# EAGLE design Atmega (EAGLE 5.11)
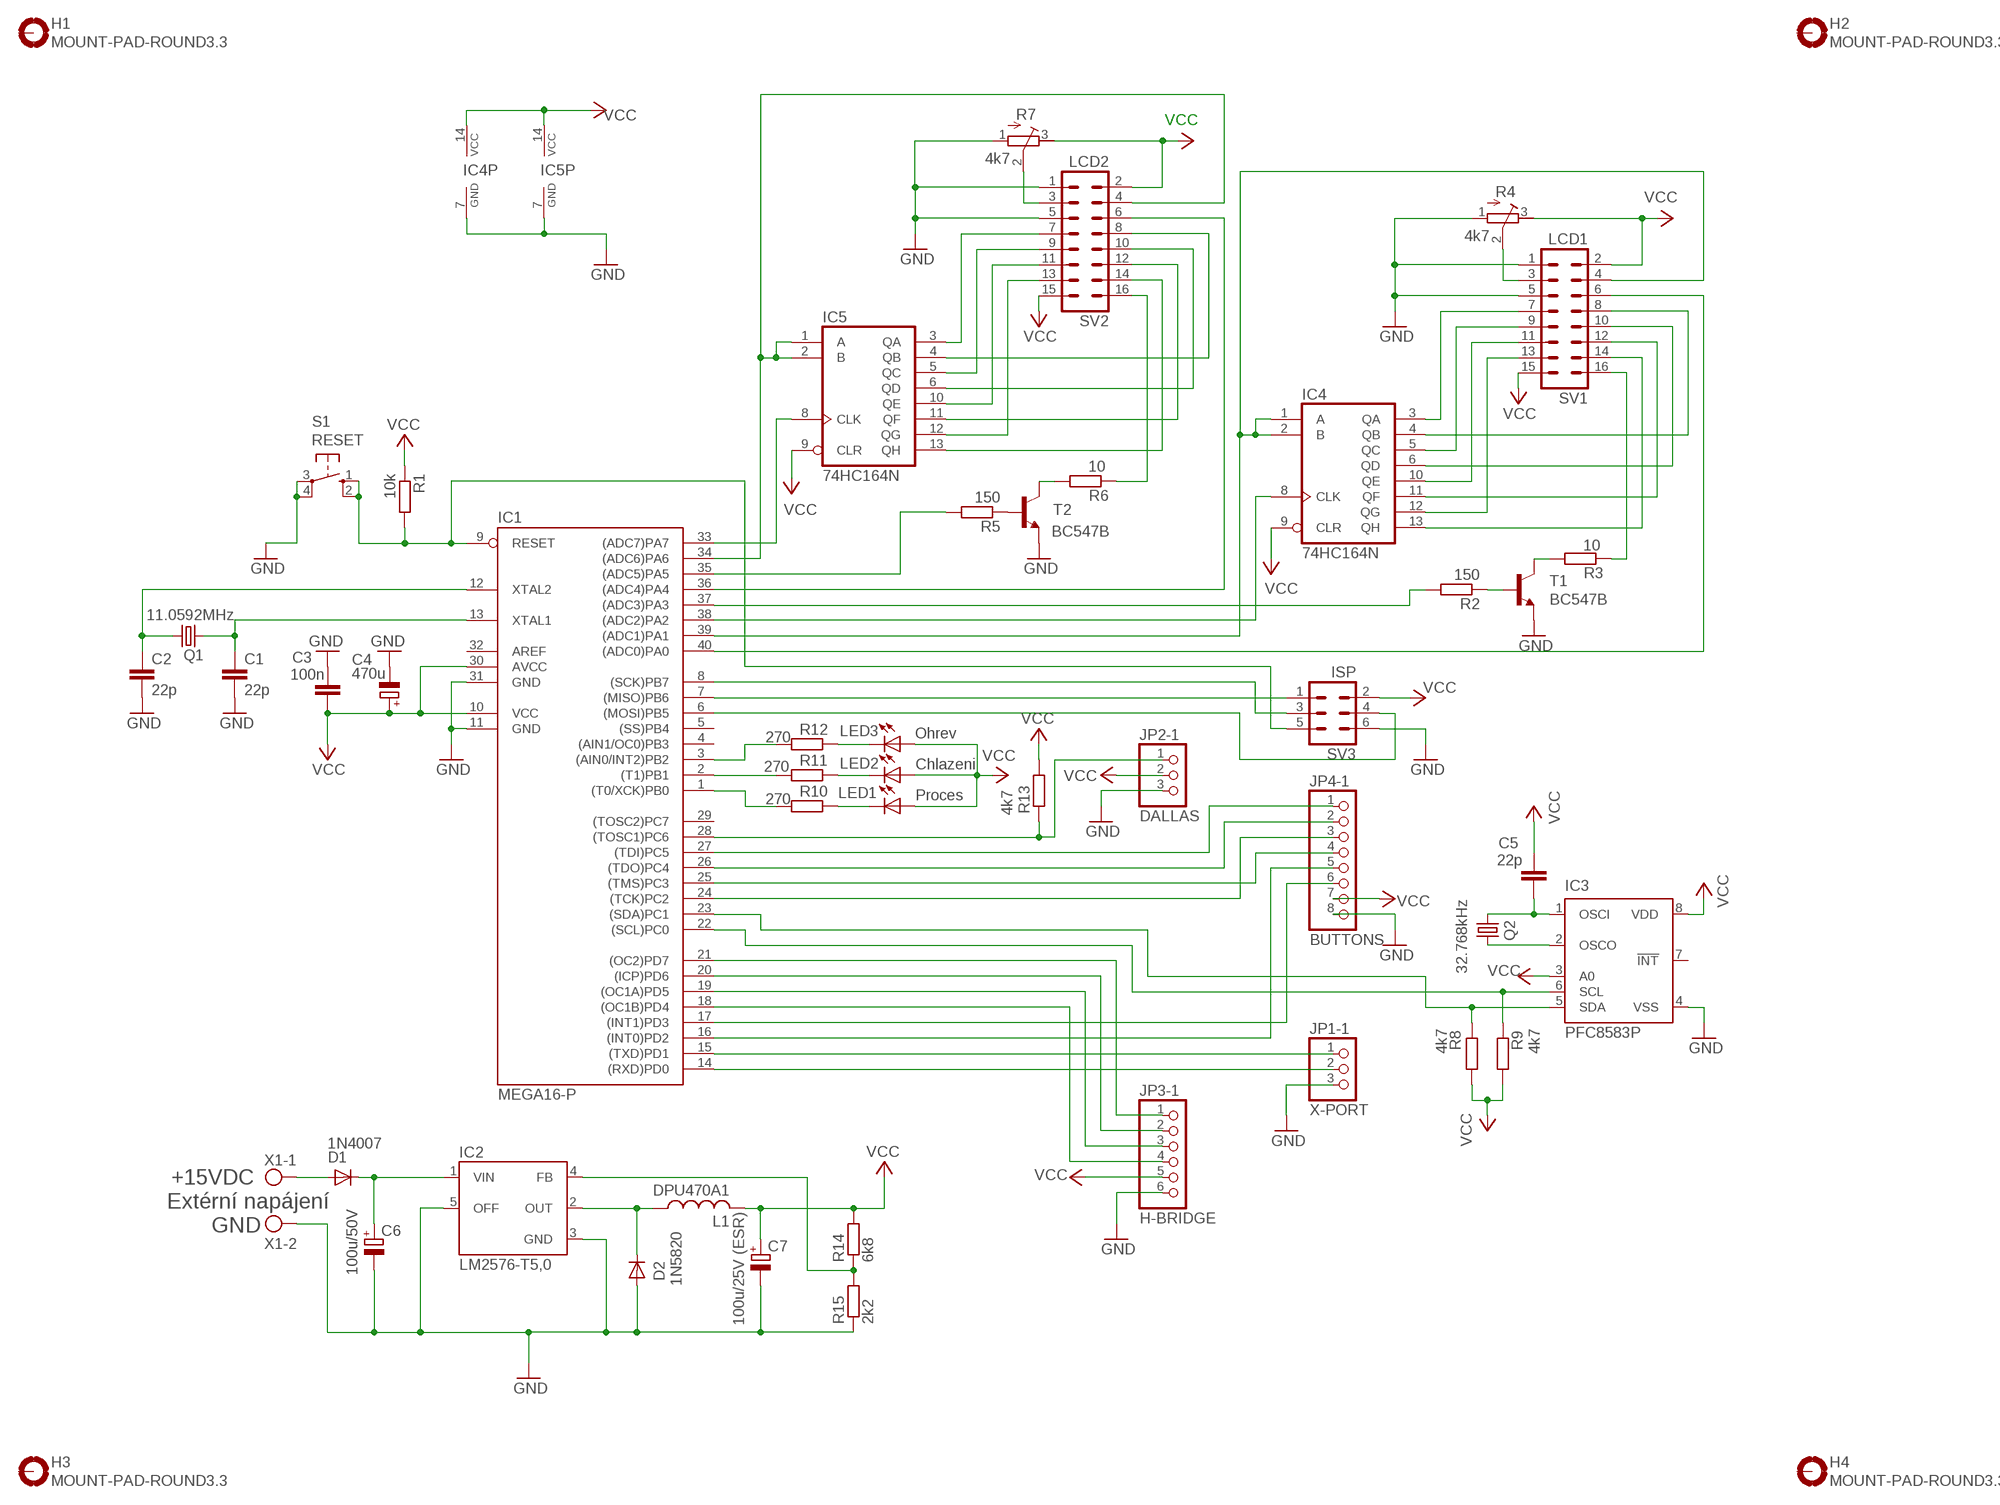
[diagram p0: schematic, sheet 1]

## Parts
C1  22p  C-EU025-030X050  [C025-030X050]
C2  22p  C-EU025-030X050  [C025-030X050]
C3  100n  C-EU025-030X050  [C025-030X050]
C4  470u  CPOL-EUE3.5-8  [E3,5-8]
C5  22p  C-EU025-030X050  [C025-030X050]
C6  100u/50V  CPOL-EUE3.5-8  [E3,5-8]
C7  100u/25V (ESR)  CPOL-EUE3.5-8  [E3,5-8]
D1  1N4007  1N4004  [DO41-10]
D2  1N5820  1N4004  [DO41-10]
H1  MOUNT-PAD-ROUND3.3  [3,3-PAD]
H2  MOUNT-PAD-ROUND3.3  [3,3-PAD]
H3  MOUNT-PAD-ROUND3.3  [3,3-PAD]
H4  MOUNT-PAD-ROUND3.3  [3,3-PAD]
IC1  MEGA16-P  [DIL40]
IC2  LM2576-T5,0  LM2576T  [TO220-5]
IC3  PFC8583P  [DIL08]
IC4  74HC164N  74AC164N  [DIL14]
IC5  74HC164N  74AC164N  [DIL14]
JP1-1  X-PORT  PINHD-1X3  [1X03]
JP2-1  DALLAS  PINHD-1X3  [1X03]
JP3-1  H-BRIDGE  PINHD-1X6  [1X06]
JP4-1  BUTTONS  PINHD-1X8  [1X08]
L1  DPU470A1  L-USIR-4  [IR-4]
LED1  Proces  LED5MM  [LED5MM]
LED2  Chlazeni  LED5MM  [LED5MM]
LED3  Ohrev  LED5MM  [LED5MM]
Q1  11.0592MHz  CRYSTALHC49U-V  [HC49U-V]
Q2  32.768kHz  CRYSTALTC26V  [TC26V]
R1  10k  R-EU_0207/7  [0207/7]
R2  150  R-EU_0207/7  [0207/7]
R3  10  R-EU_0207/7  [0207/7]
R4  4k7  R-TRIMM64Y  [RTRIM64Y]
R5  150  R-EU_0207/7  [0207/7]
R6  10  R-EU_0207/7  [0207/7]
R7  4k7  R-TRIMM64Y  [RTRIM64Y]
R8  4k7  R-EU_0207/7  [0207/7]
R9  4k7  R-EU_0207/7  [0207/7]
R10  270  R-EU_0207/7  [0207/7]
R11  270  R-EU_0207/7  [0207/7]
R12  270  R-EU_0207/7  [0207/7]
R13  4k7  R-EU_0207/7  [0207/7]
R14  6k8  R-EU_0207/7  [0207/7]
R15  2k2  R-EU_0207/7  [0207/7]
S1  RESET  10-XX  [B3F-10XX]
SV1  LCD1  ML16  [ML16]
SV2  LCD2  ML16  [ML16]
SV3  ISP  ML6  [ML6]
T1  BC547B  [TO92]
T2  BC547B  [TO92]
X1  Extérní napájení  AK300/2  [AK300/2]

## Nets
E_LCD1: IC1.40((ADC0)PA0) SV1.6
E_LCD2: IC1.36((ADC4)PA4) SV2.6
GND: C1.2 C2.2 C3.1 C4.- C6.- C7.- D2.A IC1.11(GND) IC1.31(GND) IC2.3(GND) IC2.5(OFF) IC3.4(VSS) IC4.7(GND) IC5.7(GND) JP1-1.3 JP2-1.3 JP3-1.6 JP4-1.8 R4.1(E) R7.1(E) R15.1 S1.3(P) S1.4(P1) SV1.1 SV1.5 SV2.1 SV2.5 SV3.6 T1.1(E) T2.1(E) X1.2
N$1: IC1.38((ADC2)PA2) IC4.8(CLK)
N$2: IC1.39((ADC1)PA1) IC4.1(A) IC4.2(B) SV1.4
N$3: IC1.37((ADC3)PA3) R2.2
N$4: R2.1 T1.2(B)
N$5: R3.2 T1.3(C)
N$6: R3.1 SV1.16
N$7: IC4.3(QA) SV1.7
N$8: IC4.5(QC) SV1.9
N$9: IC4.4(QB) SV1.8
N$10: IC4.6(QD) SV1.10
N$11: IC4.10(QE) SV1.11
N$12: IC4.11(QF) SV1.12
N$13: IC4.12(QG) SV1.13
N$14: IC4.13(QH) SV1.14
N$15: IC1.15((TXD)PD1) JP1-1.1
N$16: R4.2(S) SV1.3
N$17: IC1.14((RXD)PD0) JP1-1.2
N$18: IC1.33((ADC7)PA7) IC5.8(CLK)
N$19: IC1.34((ADC6)PA6) IC5.1(A) IC5.2(B) SV2.4
N$20: IC1.35((ADC5)PA5) R5.2
N$21: R5.1 T2.2(B)
N$22: R6.2 T2.3(C)
N$23: R6.1 SV2.16
N$24: IC5.3(QA) SV2.7
N$25: IC5.5(QC) SV2.9
N$26: IC5.4(QB) SV2.8
N$27: IC5.6(QD) SV2.10
N$28: IC5.10(QE) SV2.11
N$29: IC5.11(QF) SV2.12
N$30: IC5.12(QG) SV2.13
N$31: IC5.13(QH) SV2.14
N$32: R7.2(S) SV2.3
N$33: IC2.4(FB) R14.1 R15.2
N$34: C1.1 IC1.13(XTAL1) Q1.2
N$35: C2.1 IC1.12(XTAL2) Q1.1
N$36: D1.A X1.1
N$37: IC1.1((T0/XCK)PB0) R10.1
N$38: IC1.2((T1)PB1) R11.1
N$39: IC1.21((OC2)PD7) JP3-1.1
N$40: IC1.3((AIN0/INT2)PB2) R12.1
N$41: IC1.26((TDO)PC4) JP4-1.2
N$42: C5.2 IC3.1(OSCI) Q2.1
N$43: IC3.2(OSCO) Q2.2
N$44: IC1.27((TDI)PC5) JP4-1.1
N$45: D2.C IC2.2(OUT) L1.1
N$46: C6.+ D1.C IC2.1(VIN)
N$47: IC1.23((SDA)PC1) IC3.5(SDA) R8.1
N$48: IC1.22((SCL)PC0) IC3.6(SCL) R9.1
N$50: LED1.K(C) R10.2
N$51: LED2.K(C) R11.2
N$52: LED3.K(C) R12.2
N$53: IC1.24((TCK)PC2) JP4-1.3
N$54: IC1.25((TMS)PC3) JP4-1.4
N$55: IC1.16((INT0)PD2) JP4-1.5
N$56: IC1.17((INT1)PD3) JP4-1.6
N$57: IC1.6((MOSI)PB5) SV3.4
N$58: IC1.7((MISO)PB6) SV3.1
N$59: IC1.8((SCK)PB7) SV3.3
N$60: IC1.28((TOSC1)PC6) JP2-1.1 R13.1
N$61: IC1.9(RESET) R1.2 S1.1(S) S1.2(S1) SV3.5
N$62: IC1.20((ICP)PD6) JP3-1.2
N$63: IC1.19((OC1A)PD5) JP3-1.3
N$64: IC1.18((OC1B)PD4) JP3-1.4
VCC: C3.2 C4.+ C5.1 C7.+ IC1.10(VCC) IC1.30(AVCC) IC3.3(A0) IC3.8(VDD) IC4.9(CLR) IC4.14(VCC) IC5.9(CLR) IC5.14(VCC) JP2-1.2 JP3-1.5 JP4-1.7 L1.2 LED1.A LED2.A LED3.A R1.1 R4.3(A) R7.3(A) R8.2 R9.2 R13.2 R14.2 SV1.2 SV1.15 SV2.2 SV2.15 SV3.2
Unconnected: H1.B3,3(MOUNT) H2.B3,3(MOUNT) H3.B3,3(MOUNT) H4.B3,3(MOUNT) IC1.4((AIN1/OC0)PB3) IC1.5((SS)PB4) IC1.29((TOSC2)PC7) IC1.32(AREF) IC3.7(!INT)

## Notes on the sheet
- +15VDC
- GND

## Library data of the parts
C1-C3 C5 = rcl:C-EU: CAPACITOR, European symbol
C4 C6 C7 = rcl:CPOL-EU: POLARIZED CAPACITOR, European symbol
D1 D2 = diode:1N4004: DIODE
H1-H4 = holes:MOUNT-PAD-ROUND: MOUNTING PAD, round
IC1 = atmel:MEGA16-P: MICROCONTROLLER 16 Kbytes FLASH 1 kbytes SRAM 512 bytes EEPROM USART 8-channel 10 bit ADC Source: avr.lbr; MPN: ATMEGA16-16PU; OC_FARNELL: 9171142; OC_NEWARK: 01M6885
IC2 = v-reg-3:LM2576: National Semiconductor 3.0A "Simple Switcher"(c) 52kHz, Vout 1.23-37V (HV: 57V), Vin 40V (HV: 60V), 50µA standby current
IC3 = micro-philips:PFC8583: I2C-Bus CLOCK/CALENDAR; OC_FARNELL: unknown; OC_NEWARK: unknown
IC4 IC5 = 74xx-eu:74*164: 8-bit parallel out SHIFT REGISTER
JP1-1 JP2-1 = pinhead:PINHD-1X3: PIN HEADER
JP3-1 = pinhead:PINHD-1X6: PIN HEADER
JP4-1 = pinhead:PINHD-1X8: PIN HEADER
L1 = rcl:L-US: INDUCTOR, American symbol
LED1-LED3 = led:LED: LED
Q1 = crystal:CRYSTAL: CRYSTAL; OC_FARNELL: 1666969; OC_NEWARK: unknown
Q2 = crystal:CRYSTAL: CRYSTAL; OC_FARNELL: unknown; OC_NEWARK: unknown
R1-R3 R5 R6 R8-R15 = rcl:R-EU_: RESISTOR, European symbol
R4 R7 = rcl:R-TRIMM: Trimm resistor
S1 = switch-omron:10-XX: OMRON SWITCH; MPN: B3F-1000; OC_FARNELL: 176432; OC_NEWARK: 36M3542
SV1 SV2 = con-harting-ml:ML16: HARTING; OC_FARNELL: unknown; OC_NEWARK: unknown
SV3 = con-harting-ml:ML6: HARTING; OC_FARNELL: unknown; OC_NEWARK: unknown
T1 T2 = transistor-npn:BC547*: NPN Transistor
X1 = con-ptr500:AK300/2: CONNECTOR; OC_FARNELL: unknown; OC_NEWARK: unknown

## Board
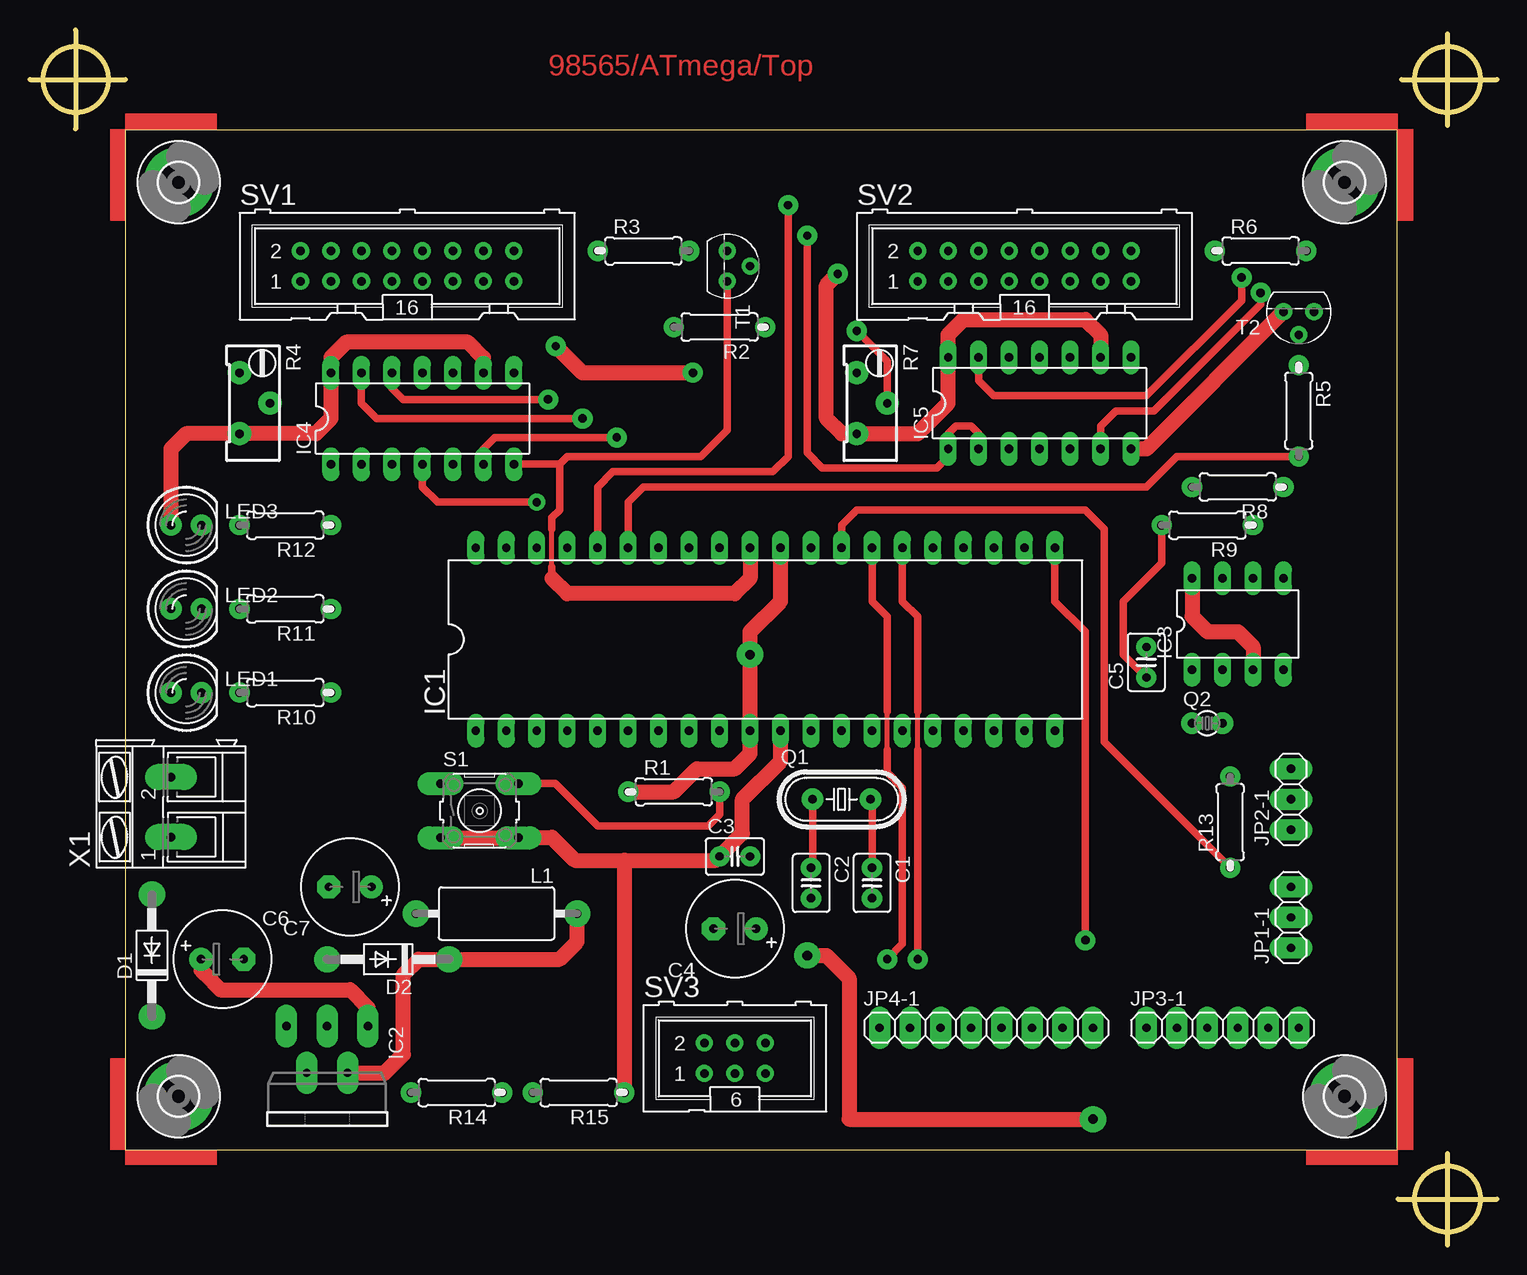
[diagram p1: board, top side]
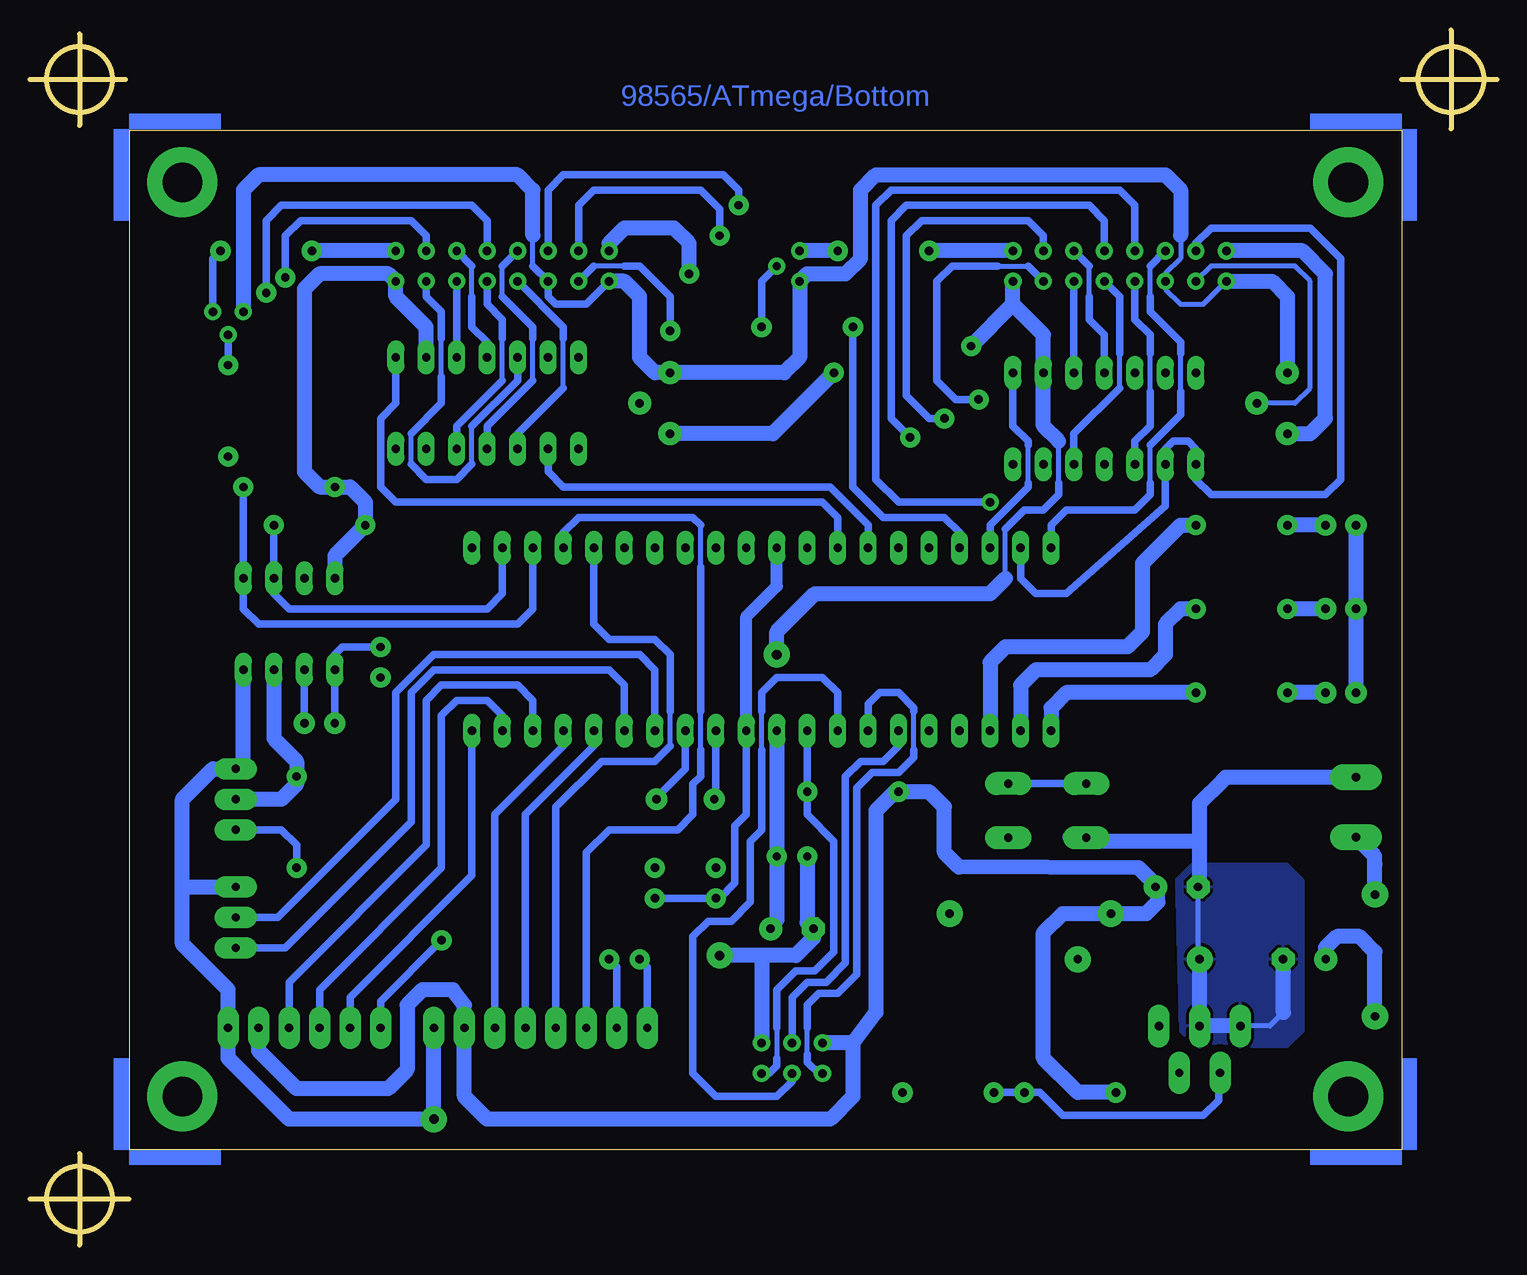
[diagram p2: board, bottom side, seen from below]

Size 122.24 x 101.28 mm. Coordinates in mm from the lower left corner, seen from the top.
Outline: 113.98,3.81 122.24,3.81
Outline: 118.11,7.62 118.11,0
Outline: 114.3,97.16 122.24,97.16
Outline: 118.11,100.97 118.11,93.34
Outline: 0,97.16 7.94,97.16
Outline: 3.81,101.28 3.81,93.03
Outline: 7.94,7.94 113.94,7.94 113.94,92.94 7.94,92.94 7.94,7.94
Outline: circle at 3.81,97.16 radius 2.73
Outline: circle at 118.11,97.16 radius 2.73
Outline: circle at 118.11,3.81 radius 2.73
Copper layers (1*16): Top 0.035mm / dielectric 1.5mm / Bottom 0.035mm
Design rules "default *": minimum track width 10mil, minimum drill 24mil, track to track 10mil, track to pad 10mil, pad to pad 10mil, via to via 8mil, smd to smd 8mil, copper to edge 40mil, drill to drill 8mil, minimum pad ring 10mil, minimum via ring 8mil, stop-mask expansion 4mil, vias tented up to drill 0mil, thermal gap 10mil

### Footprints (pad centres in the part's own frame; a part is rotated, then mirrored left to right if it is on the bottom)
C025-030X050 = drill 0.7 pad 1.676 round: 1 -1.27,0; 2 1.27,0
E3,5-8 = drill 0.7 pad 1.93 round: + -1.778,0 | drill 0.7 pad 1.93 octagon: - 1.778,0
DO41-10 = drill 0.7 pad 2.184 round: A 5.08,0; C -5.08,0
3,3-PAD = drill 3.3 pad 5.842 round: B3,3 0,0
DIL40 = drill 0.7 pad 1.422 long: 1 -24.13,-7.62; 2 -21.59,-7.62; 3 -19.05,-7.62; 4 -16.51,-7.62; 5 -13.97,-7.62; 6 -11.43,-7.62; 7 -8.89,-7.62; 8 -6.35,-7.62; 9 -3.81,-7.62; 10 -1.27,-7.62; 11 1.27,-7.62; 12 3.81,-7.62; 13 6.35,-7.62; 14 8.89,-7.62; 15 11.43,-7.62; 16 13.97,-7.62; 17 16.51,-7.62; 18 19.05,-7.62; 19 21.59,-7.62; 20 24.13,-7.62; 21 24.13,7.62; 22 21.59,7.62; 23 19.05,7.62; 24 16.51,7.62; 25 13.97,7.62; 26 11.43,7.62; 27 8.89,7.62; 28 6.35,7.62; 29 3.81,7.62; 30 1.27,7.62; 31 -1.27,7.62; 32 -3.81,7.62; 33 -6.35,7.62; 34 -8.89,7.62; 35 -11.43,7.62; 36 -13.97,7.62; 37 -16.51,7.62; 38 -19.05,7.62; 39 -21.59,7.62; 40 -24.13,7.62
TO220-5 = drill 0.7 pad 1.778 long: 1 -3.4,-8.4; 2 -1.7,-4.5; 3 0,-8.4; 4 1.7,-4.5; 5 3.4,-8.4
DIL08 = drill 0.7 pad 1.422 long: 1 -3.81,-3.81; 2 -1.27,-3.81; 3 1.27,-3.81; 4 3.81,-3.81; 5 3.81,3.81; 6 1.27,3.81; 7 -1.27,3.81; 8 -3.81,3.81
DIL14 = drill 0.7 pad 1.422 long: 1 -7.62,-3.81; 2 -5.08,-3.81; 3 -2.54,-3.81; 4 0,-3.81; 5 2.54,-3.81; 6 5.08,-3.81; 7 7.62,-3.81; 8 7.62,3.81; 9 5.08,3.81; 10 2.54,3.81; 11 0,3.81; 12 -2.54,3.81; 13 -5.08,3.81; 14 -7.62,3.81
1X03 = drill 0.7 pad 1.778 long: 1 -2.54,0; 2 0,0; 3 2.54,0
1X06 = drill 0.7 pad 1.778 long: 1 -6.35,0; 2 -3.81,0; 3 -1.27,0; 4 1.27,0; 5 3.81,0; 6 6.35,0
1X08 = drill 0.7 pad 1.778 long: 1 -8.89,0; 2 -6.35,0; 3 -3.81,0; 4 -1.27,0; 5 1.27,0; 6 3.81,0; 7 6.35,0; 8 8.89,0
IR-4 = drill 0.7 pad 2.184 round: 1 -6.705,0; 2 6.73,0
LED5MM = drill 0.7 pad 1.778 round: A -1.27,0; K 1.27,0
HC49U-V = drill 0.7 pad 1.778 round: 1 -2.413,0; 2 2.413,0
TC26V = drill 0.7 pad 1.778 round: 1 -1.27,0; 2 1.27,0
0207/7 = drill 0.7 pad 1.676 round: 1 -3.81,0; 2 3.81,0
RTRIM64Y = drill 0.7 pad 1.93 round: 1 0,-2.54; 2 -2.54,0; 3 0,2.54
B3F-10XX = drill 0.7 pad 1.93 long: 1 -3.251,2.261; 2 3.251,2.261; 3 -3.251,-2.261; 4 3.251,-2.261
ML16 = drill 0.7 pad 1.422 round: 1 -8.89,-1.27; 2 -8.89,1.27; 3 -6.35,-1.27; 4 -6.35,1.27; 5 -3.81,-1.27; 6 -3.81,1.27; 7 -1.27,-1.27; 8 -1.27,1.27; 9 1.27,-1.27; 10 1.27,1.27; 11 3.81,-1.27; 12 3.81,1.27; 13 6.35,-1.27; 14 6.35,1.27; 15 8.89,-1.27; 16 8.89,1.27
ML6 = drill 0.7 pad 1.422 round: 1 -2.54,-1.27; 2 -2.54,1.27; 3 0,-1.27; 4 0,1.27; 5 2.54,-1.27; 6 2.54,1.27
TO92 = drill 0.7 pad 1.422 round: 1 1.27,0; 2 0,1.905; 3 -1.27,0
AK300/2 = drill 0.7 pad 2.184 long: 1 -2.515,0; 2 2.489,0

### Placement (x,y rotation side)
C1  70.17,30.16 270 top
C2  65.09,30.16 270 top
C3  58.74,32.39 0 top
C4  58.74,26.35 180 top
C5  93.03,48.58 90 top
C6  16.03,23.81 0 top
C7  26.67,29.84 180 top
D1  10.16,24.13 90 top
D2  29.84,23.81 180 top
H1  12.38,12.38 0 top
H2  12.38,88.58 0 top
H3  109.54,12.38 0 top
H4  109.54,88.58 0 top
IC1  61.28,50.48 0 top
IC2  24.77,9.84 180 top
IC3  100.65,51.75 0 top
IC4  32.7,68.9 0 top
IC5  84.14,70.17 0 top
JP1-1  105.09,27.3 90 top
JP2-1  105.09,37.15 90 top
JP3-1  99.38,18.1 0 top
JP4-1  79.69,18.1 0 top
L1  38.89,27.62 180 top
LED1  13.02,46.04 0 top
LED2  13.02,53.02 0 top
LED3  13.02,60.01 0 top
Q1  67.63,37.15 0 top
Q2  98.11,43.5 0 top
R1  53.66,37.78 0 top
R2  57.47,76.52 180 top
R3  51.12,82.87 0 top
R4  17.46,70.17 180 top
R5  105.73,69.53 270 top
R6  102.55,82.87 0 top
R7  68.9,70.17 180 top
R8  100.65,63.18 180 top
R9  98.11,60.01 180 top
R10  21.27,46.04 180 top
R11  21.27,53.02 180 top
R12  21.27,60.01 180 top
R13  100.01,35.24 90 top
R14  35.56,12.7 180 top
R15  45.72,12.7 180 top
S1  37.47,36.2 0 top
SV1  31.43,81.6 0 top
SV2  82.87,81.6 0 top
SV3  58.74,15.56 0 top
T1  58.1,81.6 270 top
T2  105.73,77.79 180 top
U$1  [ANGLE-ARROW-NW1-16]  7.94,93.03 0 top
U$2  [ANGLE-ARROW-NW1-16]  113.98,93.03 270 top
U$3  [ANGLE-ARROW-NW1-16]  113.98,7.94 180 top
U$4  [ANGLE-ARROW-NW1-16]  7.94,7.94 90 top
X1  11.75,36.51 90 top

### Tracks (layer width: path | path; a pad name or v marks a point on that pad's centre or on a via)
E_LCD1
  Bottom 0.406: 28.89,79.06 28.89,81.6 | 26.35,71.12 26.35,74.3 | 28.89,63.5 28.89,66.67
  Bottom 0.61: 28.89,81.6 SV1.6 | 28.89,79.06 28.89,77.79 26.35,75.25 26.35,74.3 | 28.89,66.67 26.35,69.22 26.35,71.12 | IC1.40 37.15,60.01 35.88,61.28 30.16,61.28 28.89,62.55 28.89,63.5
E_LCD2  (via drill 0.7 pad 1.68)
  Top 0.61: v63.18,86.68 63.18,65.72 61.91,64.45 48.58,64.45 47.31,63.18 IC1.36
  Bottom 0.61: SV2.6 79.06,87.95 77.79,89.22 64.45,89.22 63.18,87.95 v63.18,86.68
GND  (via drill 0.8 pad 2.18)
  Top 0.406: 43.5,55.56 43.5,55.88 | 43.5,56.52 43.5,59.69
  Top 0.61: T1.1 58.1,67.95 55.88,65.72 44.77,65.72 44.13,65.09 | 43.5,55.88 43.5,56.52 | 43.5,59.69 43.5,60.64 44.13,61.28 44.13,65.09 | 44.13,65.09 IC4.7
  Top 1.27: T2.1 93.03,66.36 IC5.7 | IC1.11 62.55,40.32 59.37,37.15 59.37,34.29 C3.1 57.15,32.07 49.53,32.07 | v88.58,10.48 68.26,10.48 68.26,22.22 66.36,24.13 v64.77,24.13 | 43.5,55.56 44.77,54.29 58.74,54.29 60.01,55.56 IC1.31 | S1.3 S1.4 39.17,33.97 43.5,33.97 45.4,32.07 49.53,32.07 | 49.53,32.07 R15.1
  Bottom 0.406: SV1.1 24.45,78.42 26.35,78.42 27.62,79.69 SV1.5 27.62,80.96 26.35,82.23 26.35,84.14 | 80.33,81.6 80.33,84.14 | C7.- 24.89,22.99 D2.A | IC2.5 18.9,18.24 17.78,19.37
  Bottom 0.61: SV2.1 75.88,78.42 78.42,78.42 79.06,79.06 SV2.5 80.33,81.6 | C1.2 C2.2 64.77,28.89 63.5,30.16 63.5,34.93 62.55,35.88 IC1.11
  Bottom 1.016: IC1.11 62.55,52.39 60.01,54.93 IC1.31
  Bottom 1.27: R4.1 17.46,79.06 18.73,80.33 SV1.1 | 26.35,84.14 26.35,87.95 27.62,89.22 51.75,89.22 53.02,87.95 53.02,82.23 54.29,80.96 57.47,80.96 T1.1 58.1,73.98 59.37,72.71 R7.1 70.17,72.71 71.44,73.98 71.44,79.06 72.71,80.33 SV2.1 | 80.33,84.14 80.33,87.95 81.6,89.22 103.19,89.22 104.46,87.95 T2.1 | IC3.4 104.46,40.32 JP2-1.3 107,39.69 109.54,37.15 109.54,29.84 | C3.1 57.47,26.86 C4.- 56.96,25.59 58.42,24.13 61.28,24.13 | JP4-1.8 v88.58,10.48 100.65,10.48 105.73,15.56 JP3-1.6 105.73,21.27 109.54,25.08 109.54,29.84 | 35.56,33.97 33.93,33.97 S1.3 33.93,33.66 24.77,33.66 | 61.28,24.13 SV3.6 | D2.A IC2.3 IC2.5 | 17.78,19.37 17.78,22.83 C6.- | C7.- 24.89,29.97 24.77,29.97 24.77,33.66 | 109.54,29.84 JP1-1.3 | 61.28,24.13 v64.77,24.13 | 24.77,33.66 24.77,36.83 22.86,38.73 22.59,39 X1.2
  pour Bottom (isolate 0.61): 25.4,31.75 17.46,31.75 16.19,30.48 16.19,17.78 17.46,16.51 25.08,16.51 26.35,17.78 26.67,30.48
N$1
  Bottom 0.406: 39.05,63.5 39.05,66.67
  Bottom 0.61: IC4.8 40.32,68.26 39.05,66.99 39.05,66.67 | IC1.38 42.23,60.01 39.05,63.18 39.05,63.5
N$2
  Bottom 0.61: IC1.39 39.69,55.56 38.42,54.29 35.88,54.29 27.62,61.59 IC4.2 27.62,66.36 26.99,66.99 25.72,66.99 25.08,66.36 IC4.1 25.08,63.82 23.81,62.55 14.29,62.55 13.02,63.82 13.02,82.23 15.56,84.77 23.81,84.77 25.08,83.5 SV1.4
N$3
  Bottom 0.61: IC1.37 44.77,59.37 46.04,60.64 51.12,60.64 53.66,63.18 R2.2
N$4
  Bottom 0.61: T1.2 61.28,80.33 R2.1
N$5
  Bottom 1.27: R3.2 T1.3
N$6
  Bottom 1.27: SV1.16 R3.1
N$7
  Bottom 0.406: 28.89,71.12 28.89,74.3
  Bottom 0.61: SV1.7 30.16,77.15 28.89,75.88 28.89,74.3 | IC4.3 30.16,66.99 28.89,68.26 28.89,71.12
N$8
  Bottom 0.406: 31.43,71.44 31.43,74.3
  Bottom 0.61: SV1.9 31.43,79.06 31.43,74.3 | 31.43,71.44 35.24,67.63 IC4.5
N$9  (via drill 0.7 pad 1.42)
  Top 0.61: v42.23,61.91 33.97,61.91 32.7,63.18 IC4.4
  Bottom 0.61: SV1.8 30.16,86.68 31.43,87.95 50.48,87.95 51.75,86.68 51.75,63.82 49.85,61.91 v42.23,61.91
N$10  (via drill 0.7 pad 1.68)
  Top 0.61: v48.9,67.31 38.73,67.31 37.78,66.36 IC4.6
  Bottom 0.61: SV1.10 32.7,85.41 33.97,86.68 49.21,86.68 50.48,85.41 50.48,68.9 v48.9,67.31
N$11
  Bottom 0.61: IC4.10 SV1.11
N$12
  Bottom 0.406: 33.97,79.06 33.97,81.6
  Bottom 0.61: IC4.11 32.7,75.88 33.97,77.15 33.97,79.06 | 33.97,81.6 SV1.12
N$13  (via drill 0.7 pad 1.68)
  Top 0.61: v43.18,70.48 31.11,70.48 30.16,71.44 IC4.12
  Bottom 0.406: 41.59,81.6 39.05,81.6
  Bottom 0.61: 39.05,81.6 SV1.13 | 41.59,81.6 45.4,81.6 46.67,80.33 46.67,72.07 45.09,70.48 v43.18,70.48
N$14  (via drill 0.7 pad 1.68)
  Top 0.61: v46.04,68.9 28.89,68.9 27.62,70.17 IC4.13
  Bottom 0.61: SV1.14 37.78,84.14 39.05,85.41 47.94,85.41 49.21,84.14 49.21,70.8 47.31,68.9 v46.04,68.9
N$15
  Bottom 0.61: IC1.15 72.71,46.67 73.98,47.94 88.58,47.94 90.49,46.04 90.49,35.24 100.97,24.77 JP1-1.1 103.19,24.77
N$16
  Bottom 0.406: R4.2 16.83,70.17 15.56,71.44 15.56,80.33 16.83,81.6 23.81,81.6 SV1.3
N$17
  Bottom 0.61: 103.82,27.3 JP1-1.2 101.6,27.3 91.76,37.15 91.76,46.04 88.58,49.21 71.44,49.21 70.17,47.94 IC1.14
N$18
  Bottom 0.61: IC5.8 91.76,70.17 93.03,68.9 93.03,63.18 91.76,61.91 56.2,61.91 54.93,60.64 IC1.33
N$19  (via drill 0.7 pad 1.68)
  Top 0.61: v64.77,84.14 64.77,66.04 66.04,64.77 75.56,64.77 76.52,65.72 IC5.1 76.52,67.63 77.15,68.26 78.42,68.26 79.06,67.63 IC5.2
  Bottom 0.61: SV2.4 76.52,86.68 75.25,87.95 66.36,87.95 64.77,86.36 v64.77,84.14 | IC1.34 52.39,60.01 55.56,63.18 77.79,63.18 79.06,64.45 IC5.2
N$20
  Top 0.61: IC1.35 49.85,61.91 51.12,63.18 93.03,63.18 95.57,65.72 R5.2
N$21
  Bottom 0.61: R5.1 T2.2
N$22
  Bottom 0.61: T2.3 107,82.23 R6.2
N$23
  Bottom 1.27: SV2.16 R6.1
N$24
  Bottom 0.406: 77.79,71.44 77.79,75.56
  Bottom 0.61: SV2.7 77.79,76.52 77.79,75.56 | 77.79,71.44 81.6,67.63 IC5.3
N$25
  Bottom 0.406: 82.87,72.07 82.87,75.56
  Bottom 0.61: SV2.9 84.14,78.42 82.87,77.15 82.87,75.56 | 82.87,72.07 86.68,68.26 IC5.5
N$26
  Bottom 0.406: 82.87,79.06 82.87,81.6 | 80.33,72.07 80.33,75.56
  Bottom 0.61: 82.87,81.6 SV2.8 | 82.87,79.06 80.33,76.52 80.33,75.56 | 80.33,72.07 84.14,68.26 IC5.4
N$27  (via drill 0.7 pad 1.68)
  Top 0.61: v102.55,79.38 102.55,78.42 93.66,69.53 90.49,69.53 89.22,68.26 IC5.6
  Bottom 0.61: SV2.10 84.14,85.41 85.41,86.68 101.28,86.68 102.55,85.41 v102.55,79.38
N$28
  Bottom 0.61: IC5.10 SV2.11
N$29
  Bottom 0.406: 85.41,79.06 85.41,81.6
  Bottom 0.61: IC5.11 84.14,75.25 85.41,76.52 85.41,79.06 | 85.41,81.6 SV2.12
N$30
  Bottom 0.406: 87.95,72.39 87.95,75.56 | 90.49,65.09 90.49,67.63 | 85.41,65.09 85.41,68.26
  Bottom 0.61: SV2.13 89.22,79.06 87.95,77.79 87.95,75.56 | 90.49,67.63 87.95,70.17 87.95,72.39 | 90.49,65.09 89.22,63.82 86.68,63.82 85.41,65.09 | 85.41,68.26 81.6,72.07 IC5.12
N$31  (via drill 0.7 pad 1.68)
  Top 0.61: v100.97,80.64 100.97,78.74 93.03,70.8 80.33,70.8 79.06,72.07 IC5.13
  Bottom 0.61: SV2.14 89.22,84.14 90.49,85.41 99.69,85.41 100.97,84.14 v100.97,80.64
N$32  (via drill 0.7 pad 1.68)
  Top 0.61: v68.9,76.2 71.44,73.66 R7.2
  Bottom 0.406: 72.71,81.6 75.25,81.6
  Bottom 0.61: v68.9,76.2 68.9,79.06 71.44,81.6 72.71,81.6 | 75.25,81.6 SV2.3
N$33
  Bottom 0.61: R15.2 R14.1 38.1,12.7 36.2,10.79 24.45,10.79 23.18,12.07 23.18,14.23 IC2.4
N$34
  Top 0.406: 70.17,37.02 Q1.2
  Top 0.61: C1.1 70.17,37.02
  Bottom 0.406: 70.17,37.15 70.17,37.27 Q1.2
  Bottom 0.61: IC1.13 67.63,39.69 70.17,37.15
N$35
  Top 0.406: C2.1 65.21,31.56
  Top 0.61: 65.21,31.56 Q1.1
  Bottom 0.61: IC1.12 65.09,37.91 Q1.1
N$36
  Bottom 1.27: X1.1 10.19,32.41 10.16,31.75 D1.A
N$37
  Bottom 1.27: R10.1 35.88,46.04 37.15,44.77 IC1.1
N$38
  Bottom 1.27: IC1.2 39.69,46.67 38.42,47.94 28.89,47.94 27.62,49.21 27.62,51.75 26.35,53.02 R11.1
N$39  (via drill 0.7 pad 1.68)
  Top 0.61: IC1.21 85.41,53.66 87.95,51.12 v87.95,25.4
  Bottom 0.61: JP3-1.1 93.03,20.32 v87.95,25.4
N$40
  Bottom 1.27: IC1.3 42.23,48.58 40.96,49.85 30.8,49.85 29.53,51.12 29.53,56.83 26.35,60.01 R12.1
N$41  (via drill 0.7 pad 1.68)
  Top 0.406: 73.98,41.27 73.98,44.45
  Top 0.61: IC1.26 72.71,53.66 73.98,52.39 73.98,44.45 | v73.98,23.81 73.98,41.27
  Bottom 0.61: v73.98,23.81 73.34,23.18 JP4-1.2
N$42
  Bottom 0.61: Q2.1 IC3.1 96.84,49.21 96.2,49.85 C5.2
N$43
  Bottom 0.61: Q2.2 IC3.2
N$44  (via drill 0.7 pad 1.68)
  Top 0.406: 71.44,41.27 71.44,44.45
  Top 0.61: IC1.27 70.17,53.66 71.44,52.39 71.44,44.45 | v71.44,23.81 72.71,25.08 72.71,38.1 71.44,39.37 71.44,41.27
  Bottom 0.61: v71.44,23.81 70.8,23.18 JP4-1.1
N$45
  Top 1.27: IC2.2 29.58,14.34 31.11,15.88 31.11,22.54 32.39,23.81 D2.C 44.13,23.81 45.6,25.28 L1.1
N$46
  Top 1.27: IC2.1 28.16,19.78 26.67,21.27 15.84,21.27 14.61,22.54 14.26,22.89 C6.+
  Bottom 1.27: D1.C 10.16,24.45 11.43,25.72 13.33,25.72 14.29,24.77 14.29,23.84 C6.+
N$47
  Bottom 0.61: R8.1 IC3.5 104.46,53.02 103.19,51.75 81.6,51.75 80.33,53.02 IC1.23
N$48
  Bottom 0.61: R9.1 IC3.6 101.92,54.29 100.65,53.02 84.14,53.02 82.87,54.29 IC1.22
N$50
  Bottom 1.27: LED1.K R10.2
N$51
  Bottom 1.27: LED2.K R11.2
N$52
  Bottom 1.27: LED3.K R12.2
N$53
  Bottom 0.406: 66.36,41.27 66.36,44.45 | 66.36,56.52 66.36,60.01
  Bottom 0.61: 66.36,60.01 66.99,60.64 76.52,60.64 77.79,59.37 IC1.24 | JP4-1.3 75.88,32.7 73.98,34.61 68.26,34.61 66.99,35.88 66.99,38.42 66.36,39.05 66.36,41.27 | 66.36,44.45 66.36,56.52
N$54
  Bottom 0.406: 68.9,41.59 68.9,44.45
  Bottom 0.61: 68.9,41.59 70.17,40.32 74.61,40.32 78.42,36.51 JP4-1.4 | IC1.25 75.25,51.75 73.98,50.48 70.17,50.48 68.9,49.21 68.9,44.45
N$55
  Bottom 0.61: IC1.16 75.25,41.59 80.96,35.88 JP4-1.5
N$56
  Bottom 0.61: IC1.17 77.79,41.59 83.5,35.88 JP4-1.6
N$57
  Bottom 0.61: IC1.6 49.85,41.59 51.12,40.32 53.02,40.32 54.29,39.05 54.29,23.49 55.88,21.91 57.47,21.91 58.74,20.64 SV3.4
N$58
  Bottom 0.406: 57.47,15.88 57.47,18.1 | 48.58,41.27 48.58,44.45
  Bottom 0.61: SV3.1 56.52,14.29 57.47,15.24 57.47,15.88 | 57.47,18.1 57.47,20 56.52,20.96 54.93,20.96 53.34,22.54 53.34,38.1 52.07,39.37 49.85,39.37 48.58,40.64 48.58,41.27 | IC1.7 52.39,45.09 51.44,46.04 49.85,46.04 48.58,44.77 48.58,44.45
N$59
  Bottom 0.406: 61.28,41.27 61.28,44.45
  Bottom 0.61: SV3.3 58.74,13.65 60.01,12.38 65.09,12.38 66.99,14.29 66.99,25.72 65.72,26.99 63.82,26.99 62.23,28.57 62.23,33.66 61.28,34.61 61.28,41.27 | IC1.8 54.93,46.04 56.2,47.31 60.01,47.31 61.28,46.04 61.28,44.45
N$60
  Top 0.61: IC1.28 67.63,60.01 68.9,61.28 87.95,61.28 89.53,59.69 89.53,41.91 R13.1
  Bottom 0.61: R13.1 100.01,33.34 101.28,34.61 JP2-1.1
N$61
  Top 0.61: R1.2 57.47,35.88 56.52,34.93 47.31,34.93 43.78,38.46 S1.2
  Bottom 0.406: 60.01,18.1 60.01,15.56
  Bottom 0.61: S1.1 S1.2 | IC1.9 R1.2 57.47,35.88 55.24,33.66 55.24,24.45 56.83,22.86 58.42,22.86 60.01,21.27 60.01,18.1 | SV3.5 60.64,14.29 60.01,14.92 60.01,15.56
N$62
  Bottom 0.61: IC1.20 85.41,30.8 95.57,20.64 JP3-1.2 95.57,18.73
N$63
  Bottom 0.61: IC1.19 82.87,44.13 84.14,45.4 86.68,45.4 87.95,44.13 87.95,31.43 98.11,21.27 JP3-1.3 98.11,19.37
N$64
  Bottom 0.61: IC1.18 80.33,45.4 81.6,46.67 87.95,46.67 89.22,45.4 89.22,33.34 100.65,21.91 100.65,18.73 | JP3-1.4 100.65,18.73 | 100.65,18.73 100.65,19.37
VCC  (via drill 0.7 pad 1.68, 0.8 pad 2.18)
  Top 0.61: C5.1 91.12,49.21 91.12,53.66 94.3,56.83 R9.2
  Top 1.27: LED3.A 11.75,66.36 13.02,67.63 R4.3 23.81,67.63 25.08,68.9 IC4.14 25.08,73.98 26.35,75.25 36.51,75.25 37.78,73.98 IC4.9 | v67.31,80.96 66.36,80.01 66.36,68.9 67.63,67.63 R7.3 73.98,67.63 76.52,70.17 IC5.14 76.52,75.88 77.79,77.15 87.95,77.15 89.22,75.88 IC5.9 | R1.1 53.66,37.78 55.56,39.69 58.74,39.69 60.01,40.96 IC1.10 v60.01,49.21 60.01,51.12 62.55,53.66 IC1.30 | IC3.3 101.92,49.85 100.65,51.12 98.11,51.12 96.84,52.39 IC3.8 | v55.24,72.71 46.04,72.71 v43.81,74.93
  Bottom 0.406: 36.51,63.5 36.51,66.99 | 40.96,55.56 40.96,59.69
  Bottom 0.61: 40.96,59.69 39.37,61.28 37.78,61.28 36.51,62.55 36.51,63.5
  Bottom 1.27: LED1.A LED2.A LED3.A | SV1.2 16.19,82.87 14.29,80.96 14.29,68.9 15.56,67.63 R4.3 | 40.32,78.42 37.78,75.88 IC4.9 37.78,68.26 36.51,66.99 | 40.96,55.56 42.23,54.29 56.83,54.29 60.01,51.12 v60.01,49.21 | SV2.2 73.98,83.5 72.71,84.77 68.58,84.77 67.31,83.5 v67.31,80.96 | IC1.10 C3.2 60.01,27.11 C4.+ | IC3.8 96.84,57.47 R9.2 94.3,61.91 95.57,63.18 R8.2 98.11,63.18 99.38,64.45 99.38,79.69 98.11,80.96 92.39,80.96 SV2.15 91.76,79.06 89.22,76.52 IC5.9 | 53.66,16.83 53.66,12.38 55.56,10.48 84.14,10.48 86.04,12.38 JP4-1.7 86.04,20 87,21.27 89.53,21.27 90.81,20 90.81,14.61 92.39,13.02 100.01,13.02 103.19,16.19 JP3-1.5 | R7.3 60.33,67.63 v55.24,72.71 | JP2-1.2 101.28,37.15 100.01,38.42 R13.2 100.01,40.32 101.92,42.23 IC3.3 | 53.66,16.83 SV3.2 | 53.66,16.83 51.75,19.37 51.75,36.2 50.16,37.78 R1.1 47.31,37.78 46.04,36.51 46.04,32.7 44.83,31.5 29.84,31.43 28.51,30.1 28.51,29.91 C7.+ 28.26,29.65 28.26,28.57 29.21,27.62 L1.2 36.2,27.62 37.78,26.04 37.78,15.56 34.93,12.7 R14.2 | 40.32,78.42 v43.81,74.93 | 40.32,78.42 SV1.15

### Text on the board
Top: 98565/ATmega/Top
Bottom: 98565/ATmega/Bottom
